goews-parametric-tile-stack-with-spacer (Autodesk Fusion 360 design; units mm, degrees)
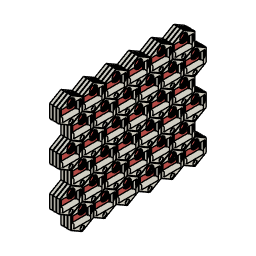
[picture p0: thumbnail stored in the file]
parameter "width" = 42
parameter "height" = 48.497
parameter "offset" = 36.373
parameter "DoubleVerticalDistance" = 72.746
sketch "Reference" plane through (0, 0, 0) normal (1, 0, 0) x axis (0, 1, 0)
  line L1 (-18, -1.6244) -> (-15.5, -4.1244)
  line L2 (-18, 9.8756) -> (-18, -1.6244)
  line L3 (-8.5448, 9.8756) -> (-18, 9.8756)
  line L4 (18, 9.8756) -> (8.5448, 9.8756)
  line L5 (18, -1.6244) -> (18, 9.8756)
  line L6 (15.5, -4.1244) -> (18, -1.6244)
  line L7 (15.5, -12.1244) -> (15.5, -4.1244)
  line L8 (-15.5, -12.1244) -> (15.5, -12.1244)
  line L9 (-15.5, -4.1244) -> (-15.5, -12.1244)
  line L10 (20.5, 11.8357) -> (20.5, -11.8357)
  line L11 (0, 23.6714) -> (20.5, 11.8357)
  line L12 (-20.5, 11.8357) -> (0, 23.6714)
  line L13 (-20.5, -11.8357) -> (-20.5, 11.8357)
  line L14 (0, -23.6714) -> (-20.5, -11.8357)
  line L15 (20.5, -11.8357) -> (0, -23.6714)
  circle C1 centre (0, 12.7017) radius 7.1612
  arc A1 centre (0, 12.7017) radius 9 clockwise from (8.5448, 9.8756) to (-8.5448, 9.8756)
  circle C2 centre (0, -18.2487) radius 4
  point P22 (-42, 24.2487)
  point P27 (-21, -12.1244)
  point P20 (0, -24.2487)
  point P23 (-21, 60.6218)
  point P21 (21, -12.1244)
  point P25 (0, 48.4974)
  point P28 (0, 24.2487)
  point P26 (21, 12.1244)
  dimension "d7" distance P22 P27 = 36.3731
  dimension "d8" distance P20 P23 = 84.8705
  dimension "d9" distance P21 P23 = 84
  dimension "d10" distance P21 P22 = 63
  dimension "d11" distance P20 P25 = 72.7461
  dimension "d17" distance P21 P27 = 42
  dimension "d18" distance P20 P28 = 48.4974
  dimension "d19" distance P23 P28 = 36.3731
  dimension "d24" distance P20 P26 = 36.3731
copy_paste_bodies "CutPasteBodies"
sketch "patch" plane through (-6, 0, 0) normal (-1, 0, 0) x axis (0, -1, 0)
  line L1 (3, 25.9808) -> (16.0118, 18.4684)
  line L2 (3, 26.0061) -> (3, 25.9808)
  line L3 (39, 26.0061) -> (3, 26.0061)
  line L4 (39, 25.9808) -> (39, 26.0061)
  line L5 (25.9882, 18.4684) -> (39, 25.9808)
  curve K1 (16.3334, 53.0977) -> (19.1178, 42.0472)
  curve K2 (22.8822, 42.0472) -> (25.6666, 53.0977)
  line L6 (0, 24.2487) -> (0, 48.4974)
  line L7 (21, 12.1244) -> (0, 24.2487)
  line L8 (42, 24.2487) -> (21, 12.1244)
  line L9 (42, 48.4974) -> (42, 24.2487)
  line L10 (21, 60.6218) -> (42, 48.4974)
  line L11 (0, 48.4974) -> (21, 60.6218)
  line L12 (7.5, 46.2487) -> (7.5, 30.2487)
  line L13 (12.4552, 46.2487) -> (7.5, 46.2487)
  line L14 (34.5, 46.2487) -> (29.5448, 46.2487)
  line L15 (34.5, 30.2487) -> (34.5, 46.2487)
  line L16 (7.5, 30.2487) -> (34.5, 30.2487)
  line L17 (9.8586, 52.0614) -> (11.841, 52.0614)
  line L18 (9.8586, 48.8529) -> (9.8586, 52.0614)
  line L19 (11.841, 48.8529) -> (9.8586, 48.8529)
  line L20 (11.841, 52.0614) -> (11.841, 48.8529)
  line L21 (32.2218, 52.0614) -> (29.7148, 52.0614)
  line L22 (32.2218, 48.4173) -> (32.2218, 52.0614)
  line L23 (29.7148, 48.4173) -> (32.2218, 48.4173)
  line L24 (29.7148, 52.0614) -> (29.7148, 48.4173)
  arc A1 centre (21, 18.1244) radius 5 clockwise from (16.0118, 18.4684) to (25.9882, 18.4684)
  arc A2 centre (21, 49.0748) radius 6.1612 clockwise from (16.3334, 53.0977) to (25.6666, 53.0977)
  arc A3 centre (21, 49.0748) radius 7.2753 clockwise from (22.8822, 42.0472) to (19.1178, 42.0472)
  circle C1 centre (21, 18.1244) radius 2
  arc A4 centre (21, 49.0748) radius 9 clockwise from (29.5448, 46.2487) to (12.4552, 46.2487)
  horizontal L17
  vertical L18
  horizontal L19
  vertical L20
  horizontal L21
  vertical L22
  horizontal L23
  vertical L24
extrude "Extrude1" add sketch "patch" profile of L17 L18 L19 L20 L21 L22 L23 L24 against normal blind 6
copy_paste_bodies "CopyPasteBodies3"
copy_paste_bodies "CopyPasteBodies4"
move "Move3"
align "Align1"
move "Move2"
combine "Combine3" bodies "Hex (1)"
rectangular_pattern "R-Pattern3" countU 3 (= "VerticalQTY / 2") uSpaceDistance 72.746 vSpaceDistance -42 bodies "Hex (10)", "Hex (11)", "Hex (8)", "Hex (14)", "Hex (15)", "Hex (1)", "Hex (18)", "Hex (19)"
combine "Combine6" bodies "Hex (22)", "Hex (2)", "Hex (27)", "Hex (18)", "Hex (31)", "Hex (11)", "Hex (10)", "Hex (8)"
sketch "Sketch4" plane through (-6, 0, 0) normal (-1, 0, 0) x axis (0, -1, 0)
  line L1 (-21, 12.1244) -> (-42, 24.2487)
  line L2 (0, 24.2487) -> (-21, 12.1244)
  line L3 (21, 12.1244) -> (0, 24.2487)
  line L4 (42, 24.2487) -> (21, 12.1244)
  line L5 (42, 48.4974) -> (42, 24.2487)
  line L6 (63, 60.6217) -> (42, 48.4974)
  line L7 (63, 84.8704) -> (63, 60.6217)
  line L8 (42, 96.9948) -> (63, 84.8704)
  line L9 (3, 25.9808) -> (16.0118, 18.4684)
  line L10 (3, 26.0061) -> (3, 25.9808)
  line L11 (39, 26.0061) -> (3, 26.0061)
  line L12 (39, 25.9808) -> (39, 26.0061)
  line L13 (25.9882, 18.4684) -> (39, 25.9808)
  curve K1 (16.3334, 53.0977) -> (19.1178, 42.0472)
  curve K2 (22.8822, 42.0472) -> (25.6666, 53.0977)
  line L14 (7.5, 46.2487) -> (7.5, 30.2487)
  line L15 (12.4552, 46.2487) -> (7.5, 46.2487)
  line L16 (34.5, 46.2487) -> (29.5448, 46.2487)
  line L17 (34.5, 30.2487) -> (34.5, 46.2487)
  line L18 (7.5, 30.2487) -> (34.5, 30.2487)
  line L19 (24, 62.3538) -> (37.0118, 54.8414)
  line L20 (24, 62.3791) -> (24, 62.3538)
  line L21 (60, 62.3791) -> (24, 62.3791)
  line L22 (60, 62.3538) -> (60, 62.3791)
  line L23 (46.9882, 54.8414) -> (60, 62.3538)
  curve K3 (37.3334, 89.4707) -> (40.1178, 78.4202)
  curve K4 (43.8822, 78.4202) -> (46.6666, 89.4707)
  line L24 (28.5, 82.6217) -> (28.5, 66.6217)
  line L25 (33.4552, 82.6217) -> (28.5, 82.6217)
  line L26 (55.5, 82.6217) -> (50.5448, 82.6217)
  line L27 (55.5, 66.6217) -> (55.5, 82.6217)
  line L28 (28.5, 66.6217) -> (55.5, 66.6217)
  line L29 (-13.5, 82.6217) -> (-13.5, 66.6217)
  line L30 (-8.5448, 82.6217) -> (-13.5, 82.6217)
  line L31 (13.5, 82.6217) -> (8.5448, 82.6217)
  line L32 (13.5, 66.6217) -> (13.5, 82.6217)
  line L33 (-13.5, 66.6217) -> (13.5, 66.6217)
  curve K5 (-4.6666, 89.4707) -> (-1.8822, 78.4202)
  curve K6 (1.8822, 78.4202) -> (4.6666, 89.4707)
  line L34 (-18, 62.3538) -> (-4.9882, 54.8414)
  line L35 (-18, 62.3791) -> (-18, 62.3538)
  line L36 (18, 62.3791) -> (-18, 62.3791)
  line L37 (18, 62.3538) -> (18, 62.3791)
  line L38 (4.9882, 54.8414) -> (18, 62.3538)
  line L39 (-34.5, 46.2487) -> (-34.5, 30.2487)
  line L40 (-29.5448, 46.2487) -> (-34.5, 46.2487)
  line L41 (-7.5, 46.2487) -> (-12.4552, 46.2487)
  line L42 (-7.5, 30.2487) -> (-7.5, 46.2487)
  line L43 (-34.5, 30.2487) -> (-7.5, 30.2487)
  curve K7 (-25.6666, 53.0977) -> (-22.8822, 42.0472)
  curve K8 (-19.1178, 42.0472) -> (-16.3334, 53.0977)
  line L44 (-39, 25.9808) -> (-25.9882, 18.4684)
  line L45 (-39, 26.0061) -> (-39, 25.9808)
  line L46 (-3, 26.0061) -> (-39, 26.0061)
  line L47 (-3, 25.9808) -> (-3, 26.0061)
  line L48 (-16.0118, 18.4684) -> (-3, 25.9808)
  line L49 (-105, 12.1244) -> (-126, 24.2487)
  line L50 (-84, 24.2487) -> (-105, 12.1244)
  line L51 (-63, 12.1244) -> (-84, 24.2487)
  line L52 (-42, 24.2487) -> (-63, 12.1244)
  line L53 (-81, 25.9808) -> (-67.9882, 18.4684)
  line L54 (-81, 26.0061) -> (-81, 25.9808)
  line L55 (-45, 26.0061) -> (-81, 26.0061)
  line L56 (-45, 25.9808) -> (-45, 26.0061)
  line L57 (-58.0118, 18.4684) -> (-45, 25.9808)
  curve K9 (-67.6666, 53.0977) -> (-64.8822, 42.0472)
  curve K10 (-61.1178, 42.0472) -> (-58.3334, 53.0977)
  line L58 (-76.5, 46.2487) -> (-76.5, 30.2487)
  line L59 (-71.5448, 46.2487) -> (-76.5, 46.2487)
  line L60 (-49.5, 46.2487) -> (-54.4552, 46.2487)
  line L61 (-49.5, 30.2487) -> (-49.5, 46.2487)
  line L62 (-76.5, 30.2487) -> (-49.5, 30.2487)
  line L63 (-60, 62.3538) -> (-46.9882, 54.8414)
  line L64 (-60, 62.3791) -> (-60, 62.3538)
  line L65 (-24, 62.3791) -> (-60, 62.3791)
  line L66 (-24, 62.3538) -> (-24, 62.3791)
  line L67 (-37.0118, 54.8414) -> (-24, 62.3538)
  curve K11 (-46.6666, 89.4707) -> (-43.8822, 78.4202)
  curve K12 (-40.1178, 78.4202) -> (-37.3334, 89.4707)
  line L68 (-55.5, 82.6217) -> (-55.5, 66.6217)
  line L69 (-50.5448, 82.6217) -> (-55.5, 82.6217)
  line L70 (-28.5, 82.6217) -> (-33.4552, 82.6217)
  line L71 (-28.5, 66.6217) -> (-28.5, 82.6217)
  line L72 (-55.5, 66.6217) -> (-28.5, 66.6217)
  line L73 (-97.5, 82.6217) -> (-97.5, 66.6217)
  line L74 (-92.5448, 82.6217) -> (-97.5, 82.6217)
  line L75 (-70.5, 82.6217) -> (-75.4552, 82.6217)
  line L76 (-70.5, 66.6217) -> (-70.5, 82.6217)
  line L77 (-97.5, 66.6217) -> (-70.5, 66.6217)
  curve K13 (-88.6666, 89.4707) -> (-85.8822, 78.4202)
  curve K14 (-82.1178, 78.4202) -> (-79.3334, 89.4707)
  line L78 (-102, 62.3538) -> (-88.9882, 54.8414)
  line L79 (-102, 62.3791) -> (-102, 62.3538)
  line L80 (-66, 62.3791) -> (-102, 62.3791)
  line L81 (-66, 62.3538) -> (-66, 62.3791)
  line L82 (-79.0118, 54.8414) -> (-66, 62.3538)
  line L83 (-118.5, 46.2487) -> (-118.5, 30.2487)
  line L84 (-113.5448, 46.2487) -> (-118.5, 46.2487)
  line L85 (-91.5, 46.2487) -> (-96.4552, 46.2487)
  line L86 (-91.5, 30.2487) -> (-91.5, 46.2487)
  line L87 (-118.5, 30.2487) -> (-91.5, 30.2487)
  curve K15 (-109.6666, 53.0977) -> (-106.8822, 42.0472)
  curve K16 (-103.1178, 42.0472) -> (-100.3334, 53.0977)
  line L88 (-123, 25.9808) -> (-109.9882, 18.4684)
  line L89 (-123, 26.0061) -> (-123, 25.9808)
  line L90 (-87, 26.0061) -> (-123, 26.0061)
  line L91 (-87, 25.9808) -> (-87, 26.0061)
  line L92 (-100.0118, 18.4684) -> (-87, 25.9808)
  line L93 (-181.5, 82.6217) -> (-181.5, 66.6217)
  line L94 (-176.5448, 82.6217) -> (-181.5, 82.6217)
  line L95 (-154.5, 82.6217) -> (-159.4552, 82.6217)
  line L96 (-154.5, 66.6217) -> (-154.5, 82.6217)
  line L97 (-181.5, 66.6217) -> (-154.5, 66.6217)
  curve K17 (-172.6666, 89.4707) -> (-169.8822, 78.4202)
  curve K18 (-166.1178, 78.4202) -> (-163.3334, 89.4707)
  line L98 (-186, 62.3538) -> (-172.9882, 54.8414)
  line L99 (-186, 62.3791) -> (-186, 62.3538)
  line L100 (-150, 62.3791) -> (-186, 62.3791)
  line L101 (-150, 62.3538) -> (-150, 62.3791)
  line L102 (-163.0118, 54.8414) -> (-150, 62.3538)
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sketch "Sketch5" plane through (-6, 0, 0) normal (-1, 0, 0) x axis (0, -1, 0)
extrude "Extrude2" new body sketch "Sketch4" along normal blind 0.4 bodies "Spacer"
sketch "Sketch6" plane through (-6.4, 0, 0) normal (-1, 0, 0) x axis (0, -1, 0)
  line L1 (-21, 12.1244) -> (-42, 24.2487)
  line L2 (0, 24.2487) -> (-21, 12.1244)
  line L3 (21, 12.1244) -> (0, 24.2487)
  line L4 (42, 24.2487) -> (21, 12.1244)
  line L5 (42, 48.4974) -> (42, 24.2487)
  line L6 (63, 60.6217) -> (42, 48.4974)
  line L7 (63, 84.8704) -> (63, 60.6217)
  line L8 (42, 96.9948) -> (63, 84.8704)
  line L9 (-105, 12.1244) -> (-126, 24.2487)
  line L10 (-84, 24.2487) -> (-105, 12.1244)
  line L11 (-63, 12.1244) -> (-84, 24.2487)
  line L12 (-42, 24.2487) -> (-63, 12.1244)
  line L13 (-189, 12.1244) -> (-210, 24.2487)
  line L14 (-168, 24.2487) -> (-189, 12.1244)
  line L15 (-147, 12.1244) -> (-168, 24.2487)
  line L16 (-126, 24.2487) -> (-147, 12.1244)
  line L17 (42, 121.2434) -> (42, 96.9948)
  line L18 (63, 133.3677) -> (42, 121.2434)
  line L19 (63, 157.6164) -> (63, 133.3677)
  line L20 (42, 169.7408) -> (63, 157.6164)
  line L21 (42, 193.9894) -> (42, 169.7408)
  line L22 (63, 206.1137) -> (42, 193.9894)
  line L23 (63, 230.3624) -> (63, 206.1137)
  line L24 (42, 242.4868) -> (63, 230.3624)
  line L25 (-210, 24.2487) -> (-210, 48.4974)
  line L26 (-189, 206.1138) -> (-189, 230.3624)
  line L27 (-210, 193.9894) -> (-189, 206.1138)
  line L28 (-210, 169.7407) -> (-210, 193.9894)
  line L29 (-189, 157.6164) -> (-210, 169.7407)
  line L30 (-189, 133.3678) -> (-189, 157.6164)
  line L31 (-210, 121.2434) -> (-189, 133.3678)
  line L32 (-210, 96.9947) -> (-210, 121.2434)
  line L33 (-189, 84.8704) -> (-210, 96.9947)
  line L34 (-189, 60.6218) -> (-189, 84.8704)
  line L35 (-210, 48.4974) -> (-189, 60.6218)
  line L36 (-189, 230.3624) -> (-168, 242.4868)
  line L37 (21, 230.3624) -> (42, 242.4868)
  line L38 (0, 242.4868) -> (21, 230.3624)
  line L39 (-21, 230.3624) -> (0, 242.4868)
  line L40 (-42, 242.4868) -> (-21, 230.3624)
  line L41 (-63, 230.3624) -> (-42, 242.4868)
  line L42 (-84, 242.4868) -> (-63, 230.3624)
  line L43 (-105, 230.3624) -> (-84, 242.4868)
  line L44 (-126, 242.4868) -> (-105, 230.3624)
  line L45 (-147, 230.3624) -> (-126, 242.4868)
  line L46 (-168, 242.4868) -> (-147, 230.3624)
chamfer "Chamfer1" distance 0.4
move "Move4"
copy_paste_bodies "CopyPasteBodies7"
move "Move7" TranslateX 6.4 TranslateY 0 TranslateZ 0
rectangular_pattern "R-Pattern4" countU 2 (= "StackHeight - 1") uSpaceDistance -6.4 vSpaceDistance 0 bodies "Spacer (1)", "Hex (2) (1)"
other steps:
base_feature "Base Feature1" bodies "Hex"
base_feature "Base Feature3" bodies "Hex (1)"
base_feature "Base Feature4" bodies "Hex (1) (1)"
base_feature "Base Feature7" bodies "Hex (2)"
named bodies: "Hex", "Hex (1)", "Hex (8)", "Hex (1) (1)", "Spacer", "Spacer (1)", "Hex (2)", "Hex (3)", "Hex (4)", "Hex (10)", "Hex (11)", "Hex (14)", "Hex (15)", "Hex (18)", "Hex (19)", "Hex (22)", "Hex (23)", "Hex (26)", "Hex (27)", "Hex (30)", "Hex (31)", "Hex (2) (1)"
